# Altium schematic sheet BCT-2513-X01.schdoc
size 297 x 209 mm; Symbol: Drawing-Symbol_A4; Version: V1.0; Page Size: A4; @Project Name: BM2513-24-1; @Update Date: 2026-09-02; @Create Date: 2026-09-01; Device: Drawing-Symbol_A4; @Board Name: BCT-2513-X01; @Page Name: P1; @Create Time: 14:26:58; @Page Count: 1; @Page No: 1; @Schematic Name: BCT-2513-X01; @Update Time: 13:40:29; @Assembly Variant: Basic; Border: 1; Title Block Position: 3; Size: A4; Width: 1170; Height: 825; Region Start: 1; X Region Count: 6; Y Region Count: 4; Blade Width: 10
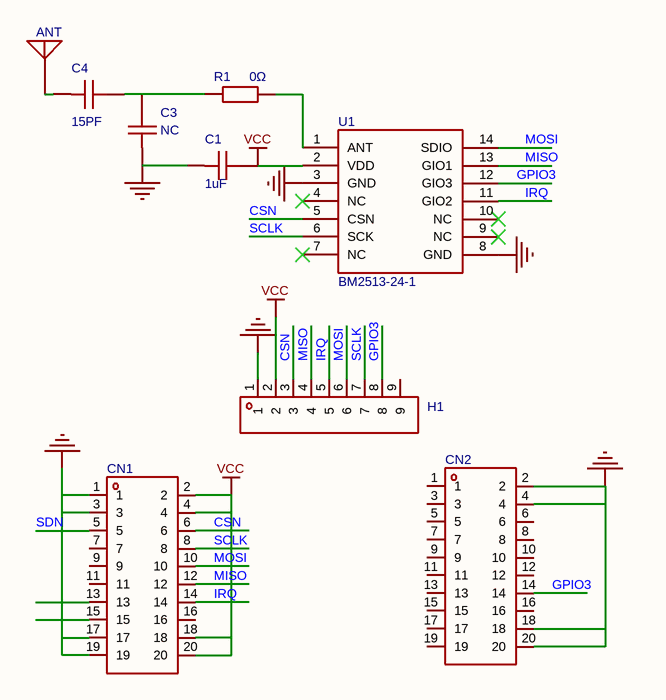
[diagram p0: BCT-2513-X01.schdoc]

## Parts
ANT  VG868SNX18-5W2  [ANT-TH_VG868SNX18-5W2]  (value not drawn)
C1  1uF  [0402C]
C3  NC  [0402C]
C4  15PF  [0402C]
CN1  2345-210MG3DUNP3  [BB02-CL]  (value not drawn)
CN2  2345-210MG3DUNP3  [BB02-CL]  (value not drawn)
H1  PZ254V-11-09P  [HDR-TH_9P-P2.54-V-M]  (value not drawn)
R1  0Ω  [0402L]
U1  (no value)  [BM2513-24-1]

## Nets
GND: C1.2 C3.2 CN1.1 CN1.3 CN1.17 CN1.19 CN2.2 CN2.4 CN2.18 CN2.20 H1.1 U1.3(GND) U1.8(GND)
VCC: C1.1 CN1.2 CN1.4 CN1.18 CN1.20 H1.2 U1.2(VDD)
CSN: CN1.6 H1.3 U1.5(CSN)
GPIO3: CN2.14 H1.8 U1.12(GIO3)
IRQ: CN1.14 H1.5 U1.11(GIO2)
MISO: CN1.12 H1.4 U1.13(GIO1)
MOSI: CN1.10 H1.6 U1.14(SDIO)
SCLK: CN1.8 H1.7 U1.6(SCK)
SDN: CN1.5
NetANT_1: ANT.1 C4.2
NetC3_1: C3.1 C4.1 R1.2
NetR1_1: R1.1 U1.1(ANT)

Not connected (* = marked no-connect by the designer): CN1 7 9 11 13 15 16; CN2 1 3 5 6 7 8 9 10 11 12 13 15 16 17 19; H1 9; U1 4(NC)* 7(NC)* 9(NC)* 10(NC)*

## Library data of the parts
ANT = VG868SNX18-5W2: 天线类型:弹簧天线;中心频率:868MHz;带宽:40MHz;增益:2dBi;功率:50W;驻波比:2;; Manufacturer: Vollgo(沃进); AddInBom: yes; ModelId: f24f990dc2914569989b7974a408a8500819f05c4eef4c71ace90d822a990e87; ModelTransform: 242.60325,655.79215,0,90,0,0,314.961,0,-106.299; Antenna Type: 弹簧天线; Frequency(Center/Band): 868MHz; Bandwidth: 40MHz; Peak Gain: 2dBi; Impedance: 50Ω; Power: 50W; VSWR: 2
C1 = CL10A105KB8NNNC: 容值:1uF;精度:±10%;额定电压:50V;温度系数:X5R;; Manufacturer: SAMSUNG(三星); 3D Model: ac125912035d415993ca9572d50418b1; 3D Model Transform: 62.992,31.496,0,0,0,0,0,0,0; Tolerance: ±10%; Voltage Rating: 50V; Temperature Coefficient: X5R; AddInBom: yes; ModelName: C0603_L1.6-W0.8-H0.8
C3 C4 = CL05A105KA5NQNC: 容值:1uF;精度:±10%;额定电压:25V;温度系数:X5R;; Manufacturer: SAMSUNG(三星); 3D Model: 36a51122f27c49738f86b3bfa98863e0; 3D Model Transform: 39.37,19.685,0,0,0,0,0,0,0; Tolerance: ±10%; Voltage Rating: 25V; Temperature Coefficient: X5R; AddInBom: yes; ModelName: C0402_L1.0-W0.5-H0.5
CN1 CN2 = 2345-210MG3DUNP3: 排数:双排;总孔位数:20P;间距:1.27mm;插孔结构:2x10P;行距:1.27mm;安装类型:立贴;圆孔/方孔:方孔;额定电流:1A;额定电压:-;插孔方向:顶部;塑高:4.57mm;工作温度范围:-40℃~+105℃;; Manufacturer: Wcon(维峰电子); 3D Model: 2585ed06fa9d440a83fe7daa0661b53f; 3D Model Transform: 514.9596,164.9603,0,0,0,0,0,-0.002,0; Number of Holes: 20P; Pitch: 1.27mm; Holes Structure: 2x10P; Circular Hole / Square Hole: 方孔; Current Rating (Max): 1A; Holes Direction: 顶部; AddInBom: yes; ModelName: CONN-SMD_2345-210MG3DUNP3
H1 = PZ254V-11-09P: 插针结构:1x9P;间距:2.54mm;行距:-;圆针/方针:方针;安装方式:直插;排数:单排;总PIN位数:9P;额定电流:-;额定电压:-;配合针长度:6mm;塑高:2.5mm;端接针长度:3mm;触头材质:黄铜;触头镀层:-;工作温度:-40℃~+105℃;颜色:黑色;; Manufacturer: XFCN(兴飞); 3D Model: b5c1e988b3bb4503807579736b357ad0; 3D Model Transform: 890.15562,98.425,0,0,0,0,0,0,-118.11; Pin Structure: 1x9P; Pitch: 2.54mm; Circluar Pins/Square Pins: 方针; AddInBom: yes; ModelName: HDR-TH_9P-P2.54-M-LI-1X9P
R1 = 0402WGF0000TCE: 电阻类型:厚膜电阻;阻值:0Ω;精度:±1%;功率:62.5mW;工作电压:50V;温度系数:±800ppm/℃;; Manufacturer: UNI-ROYAL(厚声); 3D Model: 98c88bc2b9094f218f3a3e30a7012738; 3D Model Transform: 39.37,19.685,0,0,0,0,0,0,0; Tolerance: ±1%; Power(Watts): 62.5mW; Voltage-Supply(Max): 50V; AddInBom: yes; ModelName: R0402_L1.0-W0.5-H0.4
U1 = BM2513-24-1: AddInBom: yes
